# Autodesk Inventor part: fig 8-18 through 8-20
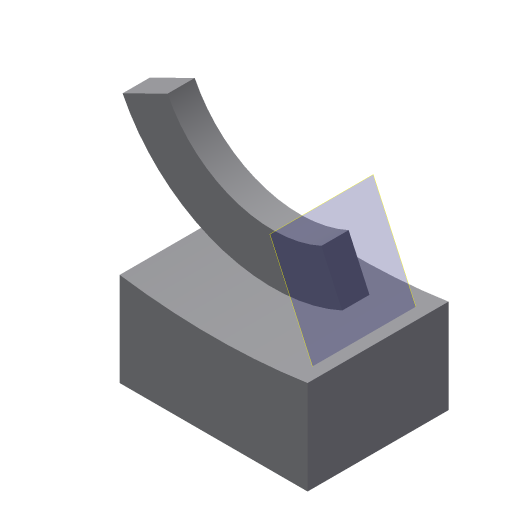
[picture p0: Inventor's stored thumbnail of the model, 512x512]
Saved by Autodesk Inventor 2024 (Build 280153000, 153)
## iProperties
Created: 2010-03
Part Number: fig 8-18 through 8-20
Document SubType Name: Modeling
Designer: CADSoft
Density: 1 g/cm^3
Material: Generic
Appearance: Default
Author: CADSoft
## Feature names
1. Extrusion1
2. Sweep3
## Parameters: d10 = 0, d13 = 0, d14 = 0
